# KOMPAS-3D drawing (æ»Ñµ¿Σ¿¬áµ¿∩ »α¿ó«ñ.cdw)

Referenced files: 1.cdw
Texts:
  ПЛК.303341.01 СП
  Привод ленточного   конвейера
  Назаров Андрей
  Noncommercial version
  Привод ленточного
  конвейера
  Муфта упругая втулочно-
  Электродвигатель 4А112МВ6УЗ
  ПШП.РЧО.140.00.00 СП-
  ПЛК.303341.01  СБ
  Документация
  Сборочный чертеж
  Редуктор цилиндрический
  пальцевая ГОСТ 21424-75
  Болты ГОСТ 7798-75
  М16х1.25-6gx55.109.40X.016
  М12х1.25-6gx40.109.40X.016
  М8х1.25-6gx15.109.40X.016
  Гайки ГОСТ 5950-70
  двухступенчатый
  Вавилин В.В
  ПЛК.303341.01 ПЗ
  ПЛК.303120.01 СБ
  ПЛК.02.01.00 СБ
  ПЛК.02.01.00.01
  Расчетно-поясниельная записка
  Сборочные единицы
  Рама сварная
  Детали
  Кожух защитный
  Сталь 45
Dimensions and other numbers on the sheet: 1:1; 2; 1; 6; 4; 10; 7; 9; 3; 5; 8; 0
